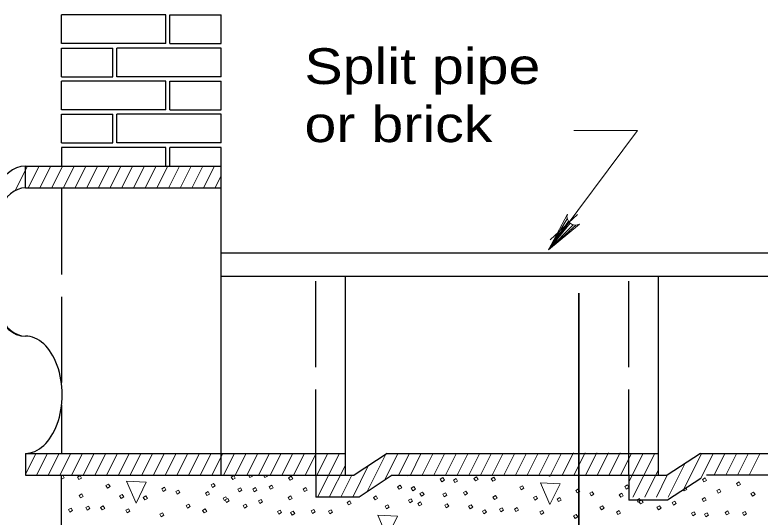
# Model space of a CAD drawing. Extents: x 750.7 to 784.7, y 860.1 to 882.1.
# Drawn here: x 753.794 to 757.13, y 863.297 to 865.543 of the extents above; entities that cross this region are included whole.
import ezdxf

# ---------------------------------------------------------------- set-up
doc = ezdxf.new("R2010")
doc.units = 0
doc.header["$LTSCALE"] = 0.064
doc.linetypes.add('LONG_DASHED', pattern=[7.5, 6, -1.5])
doc.layers.add('1', color=7, linetype='Continuous', lineweight=13)

msp = doc.modelspace()

# ---------------------------------------------------------------- linework, layer by layer
at = {"layer": '1', "lineweight": 25}
for p, q in [((754.71817, 865.41542), (754.71817, 865.5435)), ((754.23292, 865.26717), (754.23292, 865.39525)), ((754.48808, 865.41542), (754.71817, 865.41542)), ((754.00283, 865.26717), (754.23292, 865.26717)), ((754.71817, 865.11892), (754.71817, 865.247)), ((754.23292, 864.97067), (754.23292, 865.09875)), ((754.48808, 865.11892), (754.71817, 865.11892)), ((754.00283, 864.97067), (754.23292, 864.97067)), ((754.47042, 864.95042), (754.00275, 864.95042)), ((754.00275, 864.95042), (754.00275, 864.86825)), ((754.47042, 864.86733), (754.47042, 864.95042)), ((754.48808, 864.86733), (754.48808, 864.95042)), ((754.71817, 864.95042), (754.48808, 864.95042)), ((754.71817, 864.86733), (754.71817, 864.95042)), ((753.84092, 864.86733), (754.71817, 864.86733)), ((753.84092, 864.76942), (753.84092, 864.86733)), ((754.71817, 864.76942), (754.71817, 864.86733)), ((753.84092, 864.76942), (754.71817, 864.76942)), ((754.71817, 864.4795), (757.91908, 864.4795)), ((754.71817, 864.375), (758.05858, 864.375)), ((755.27333, 863.48375), (755.27333, 864.375)), ((756.67542, 863.48367), (756.67542, 864.375)), ((753.84092, 863.58175), (753.84092, 863.48383)), ((753.84092, 863.58175), (755.27333, 863.58175)), ((755.461, 863.58175), (755.3125, 863.48375)), ((755.461, 863.58175), (756.67542, 863.58175)), ((756.86317, 863.58175), (756.71458, 863.48367)), ((756.86317, 863.58175), (758.05858, 863.58175)), ((754.00275, 862.95208), (754.00275, 863.48375)), ((754.71817, 863.48375), (755.3125, 863.48375)), ((755.14075, 863.48375), (755.14075, 863.38575)), ((755.48358, 863.48375), (755.33517, 863.38575)), ((755.48358, 863.48375), (756.67542, 863.48375)), ((756.54283, 863.48367), (756.71458, 863.48367)), ((756.54283, 863.48367), (756.54283, 863.37175)), ((756.86442, 863.46967), (756.71608, 863.37175)), ((757.926, 863.48367), (756.88958, 863.48367)), ((755.33517, 863.38575), (755.14075, 863.38575)), ((756.71608, 863.37175), (756.54283, 863.37175))]:
    msp.add_line(p, q, dxfattribs=at)
at = {"layer": '1'}
for p, q in [((753.79575, 864.7575), (753.85067, 864.86733)), ((753.854, 864.76942), (753.903, 864.86733)), ((753.90633, 864.7695), (753.95525, 864.86733)), ((753.95867, 864.76967), (754.0075, 864.86733)), ((754.01108, 864.76975), (754.05983, 864.86733)), ((754.06317, 864.76942), (754.11208, 864.86733)), ((754.11542, 864.76942), (754.16442, 864.86733)), ((754.16775, 864.76942), (754.21667, 864.86733)), ((754.22, 864.76942), (754.269, 864.86733)), ((754.27233, 864.76942), (754.32125, 864.86733)), ((754.32458, 864.76942), (754.37358, 864.86733)), ((754.37683, 864.76942), (754.42583, 864.86733)), ((754.42917, 864.76942), (754.47808, 864.86733)), ((754.48117, 864.76883), (754.53042, 864.86733)), ((754.5335, 864.769), (754.58267, 864.86733)), ((754.58592, 864.76908), (754.635, 864.86733)), ((754.63825, 864.76925), (754.68725, 864.86733)), ((754.69058, 864.76933), (754.71817, 864.82458)), ((756.26667, 864.63125), (756.18308, 864.49258)), ((756.31217, 864.651), (756.19092, 864.53717)), ((756.27183, 864.62), (756.18308, 864.49258)), ((756.27967, 864.61158), (756.18308, 864.49258)), ((756.29258, 864.60475), (756.18308, 864.49258)), ((756.3045, 864.603), (756.18308, 864.49258)), ((753.84092, 863.488), (753.88783, 863.58175)), ((753.89117, 863.48383), (753.94008, 863.58175)), ((753.94342, 863.48383), (753.99242, 863.58175)), ((753.99575, 863.48383), (754.04467, 863.58175)), ((754.048, 863.48383), (754.097, 863.58175)), ((754.10025, 863.48383), (754.14925, 863.58175)), ((754.15258, 863.48383), (754.2015, 863.58175)), ((754.20483, 863.48383), (754.25383, 863.58175)), ((754.25717, 863.48383), (754.30608, 863.58175)), ((754.30942, 863.48383), (754.35842, 863.58175)), ((754.36175, 863.48383), (754.41067, 863.58175)), ((754.414, 863.48383), (754.463, 863.58175)), ((754.46633, 863.48383), (754.51525, 863.58175)), ((754.51858, 863.48383), (754.56758, 863.58175)), ((754.57083, 863.48383), (754.61983, 863.58175)), ((754.62317, 863.48383), (754.67208, 863.58175)), ((754.67542, 863.48383), (754.72442, 863.58175)), ((754.72775, 863.48383), (754.77667, 863.58175)), ((754.78008, 863.484), (754.829, 863.58175)), ((754.83242, 863.48408), (754.88125, 863.58175)), ((754.88475, 863.48417), (754.93358, 863.58175)), ((754.93708, 863.48433), (754.98583, 863.58175)), ((754.98942, 863.48442), (755.03817, 863.58175)), ((755.04183, 863.4845), (755.09042, 863.58175)), ((755.09417, 863.48467), (755.14267, 863.58175)), ((755.146, 863.48375), (755.195, 863.58175)), ((755.14933, 863.38575), (755.24725, 863.58175)), ((755.36992, 863.40867), (755.45642, 863.58175)), ((755.44792, 863.46017), (755.50875, 863.58192)), ((755.512, 863.48375), (755.56108, 863.582)), ((755.56425, 863.48375), (755.61342, 863.58208)), ((755.61658, 863.48375), (755.66583, 863.58225)), ((755.66883, 863.48375), (755.71817, 863.58233)), ((755.72117, 863.48375), (755.7705, 863.5825)), ((755.77342, 863.48375), (755.82283, 863.58258)), ((755.82567, 863.48375), (755.87517, 863.58267)), ((755.878, 863.48375), (755.9275, 863.58283)), ((755.93025, 863.48375), (755.97983, 863.58292)), ((755.98258, 863.48375), (756.03217, 863.583)), ((756.03483, 863.48375), (756.08458, 863.58317)), ((756.08717, 863.48367), (756.13692, 863.58325)), ((756.13942, 863.48375), (756.18925, 863.58342)), ((756.19175, 863.48367), (756.24158, 863.5835)), ((756.244, 863.48367), (756.29392, 863.58358)), ((756.29625, 863.48367), (756.34625, 863.58375)), ((756.34858, 863.48367), (756.39858, 863.58383)), ((756.40083, 863.48367), (756.45092, 863.58392)), ((756.45317, 863.48367), (756.50333, 863.58408)), ((756.50542, 863.48367), (756.55442, 863.58175)), ((756.54283, 863.454), (756.60675, 863.58175)), ((756.561, 863.38575), (756.659, 863.58175)), ((756.78642, 863.41817), (756.86817, 863.58183)), ((756.86442, 863.46967), (756.9205, 863.58192)), ((756.92375, 863.48367), (756.97283, 863.582)), ((756.976, 863.48367), (757.02525, 863.58217)), ((757.02825, 863.48367), (757.07758, 863.58225)), ((757.08058, 863.48367), (757.12992, 863.58233)), ((755.20158, 863.38575), (755.27333, 863.52933)), ((755.30617, 863.38575), (755.37617, 863.52575)), ((756.71792, 863.38575), (756.79258, 863.53525)), ((756.61333, 863.38575), (756.67542, 863.50992)), ((754.00275, 863.48075), (754.008, 863.48375)), ((755.25383, 863.38575), (755.30283, 863.48375)), ((756.66558, 863.38575), (756.71458, 863.48375)), ((754.73208, 863.37), (754.72592, 863.38083)), ((756.58475, 863.36267), (756.57858, 863.3735))]:
    msp.add_line(p, q, dxfattribs=at)
at = {"layer": '1', "linetype": 'LONG_DASHED', "lineweight": 25}
for p, q in [((754.00275, 864.76642), (754.00275, 863.58175)), ((755.14075, 863.48375), (755.14075, 864.375)), ((756.54283, 863.48367), (756.54283, 864.375))]:
    msp.add_line(p, q, dxfattribs=at)
at = {"layer": '1', "lineweight": 35}
msp.add_line((756.31867, 862.75308), (756.31867, 864.29933), dxfattribs=at)
at = {"layer": '1', "lineweight": 25}
for points in [[(754.47042, 865.4155), (754.47042, 865.5435), (754.00275, 865.5435)], [(754.47042, 865.4155), (754.00275, 865.4155), (754.00275, 865.5435)], [(754.48808, 865.41542), (754.48808, 865.5435), (754.71817, 865.5435)], [(754.00283, 865.26717), (754.00283, 865.39525), (754.23292, 865.39525)], [(754.71817, 865.26717), (754.71817, 865.39525), (754.2505, 865.39525)], [(754.71817, 865.26717), (754.2505, 865.26717), (754.2505, 865.39525)], [(754.47042, 865.11892), (754.47042, 865.247), (754.00275, 865.247)], [(754.47042, 865.11892), (754.00275, 865.11892), (754.00275, 865.247)], [(754.48808, 865.11892), (754.48808, 865.247), (754.71817, 865.247)], [(754.00283, 864.97067), (754.00283, 865.09875), (754.23292, 865.09875)], [(754.71817, 864.97067), (754.71817, 865.09875), (754.2505, 865.09875)], [(754.71817, 864.97067), (754.2505, 864.97067), (754.2505, 865.09875)], [(753.84092, 863.48383), (754.71817, 863.48383), (754.71817, 864.76942)]]:
    msp.add_lwpolyline(points, dxfattribs=at)
at = {"layer": '1'}
for points in [[(756.18308, 864.49258), (756.58175, 865.02675), (756.29592, 865.02675)], [(756.32217, 864.60783), (756.18308, 864.49258), (756.26717, 864.65242)], [(754.0085, 863.48375), (754.01467, 863.47275), (754.00283, 863.466), (754.00275, 863.46617)], [(754.856, 863.48375), (754.858, 863.48017), (754.84617, 863.4735), (754.84033, 863.48375)], [(754.92292, 863.48375), (754.92467, 863.4805), (754.91283, 863.47383), (754.90725, 863.48375)], [(755.554, 863.48375), (755.55075, 863.48183), (755.54967, 863.48375)], [(756.1945, 863.48375), (756.187, 863.47942), (756.18458, 863.48375)], [(756.79908, 863.42658), (756.8025, 863.42058), (756.79067, 863.41383), (756.78775, 863.41908)], [(754.72592, 863.38083), (754.73783, 863.38758), (754.741, 863.38192)], [(756.57858, 863.3735), (756.5905, 863.38025), (756.59367, 863.37458)]]:
    msp.add_lwpolyline(points, dxfattribs=at)
for points in [[(754.07408, 863.4755), (754.08592, 863.48225), (754.09233, 863.471), (754.08042, 863.46425)], [(754.76267, 863.47558), (754.7745, 863.48225), (754.78083, 863.471), (754.769, 863.46433)], [(755.0195, 863.47258), (755.03133, 863.47933), (755.03775, 863.46808), (755.02583, 863.46142)], [(755.6985, 863.4665), (755.71033, 863.47325), (755.71667, 863.462), (755.70483, 863.45525)], [(755.75725, 863.46208), (755.76908, 863.46883), (755.77542, 863.45758), (755.76358, 863.45083)], [(755.84917, 863.46992), (755.861, 863.47667), (755.86742, 863.46542), (755.8555, 863.45867)], [(755.92675, 863.46817), (755.93858, 863.47492), (755.945, 863.46367), (755.93308, 863.45692)], [(756.87217, 863.46525), (756.88408, 863.472), (756.89042, 863.46075), (756.8785, 863.45408)], [(754.20183, 863.43783), (754.21367, 863.4445), (754.22008, 863.43325), (754.20817, 863.42658)], [(754.29417, 863.45725), (754.33675, 863.35975), (754.38233, 863.4535)], [(754.45192, 863.42325), (754.46375, 863.42992), (754.47008, 863.41867), (754.45825, 863.412)], [(754.672, 863.441), (754.68383, 863.44775), (754.69017, 863.4365), (754.67833, 863.42975)], [(754.79208, 863.42142), (754.804, 863.42817), (754.81033, 863.41692), (754.79842, 863.41017)], [(754.85883, 863.42175), (754.87067, 863.4285), (754.877, 863.41725), (754.86517, 863.4105)], [(754.93167, 863.43242), (754.9435, 863.43917), (754.94983, 863.42792), (754.938, 863.42117)], [(755.08392, 863.42233), (755.09583, 863.429), (755.10217, 863.41775), (755.09025, 863.41108)], [(755.50742, 863.43225), (755.51925, 863.439), (755.52558, 863.42775), (755.51375, 863.421)], [(755.56842, 863.42617), (755.58025, 863.43292), (755.58667, 863.42167), (755.57475, 863.41492)], [(756.0545, 863.4305), (756.06633, 863.43717), (756.07275, 863.42592), (756.06083, 863.41925)], [(756.14683, 863.44992), (756.18942, 863.35242), (756.235, 863.44617)], [(756.52467, 863.43367), (756.5365, 863.44042), (756.54283, 863.42917), (756.531, 863.42242)], [(757.024, 863.4475), (757.03592, 863.45425), (757.04225, 863.443), (757.03033, 863.43625)], [(754.08158, 863.39367), (754.09342, 863.40033), (754.09975, 863.38908), (754.08792, 863.38242)], [(754.263, 863.39142), (754.27483, 863.39817), (754.28117, 863.38692), (754.26933, 863.38017)], [(754.36883, 863.38467), (754.38067, 863.39142), (754.387, 863.38017), (754.37517, 863.37342)], [(754.51442, 863.41075), (754.52625, 863.4175), (754.53258, 863.40625), (754.52075, 863.3995)], [(754.64683, 863.40417), (754.65867, 863.41092), (754.665, 863.39967), (754.65317, 863.39292)], [(755.01733, 863.38458), (755.02925, 863.39133), (755.03558, 863.38008), (755.02375, 863.37333)], [(755.39983, 863.38475), (755.41167, 863.39142), (755.418, 863.38017), (755.40617, 863.3735)], [(755.60742, 863.40208), (755.61925, 863.40883), (755.62558, 863.39758), (755.61375, 863.39092)], [(755.70958, 863.39883), (755.72142, 863.4055), (755.72775, 863.39425), (755.71592, 863.38758)], [(755.8015, 863.40658), (755.81333, 863.41333), (755.81967, 863.40208), (755.80783, 863.39542)], [(755.93425, 863.38633), (755.94608, 863.393), (755.95242, 863.38175), (755.94058, 863.37508)], [(756.30458, 863.41592), (756.31642, 863.42258), (756.32275, 863.41133), (756.31092, 863.40467)], [(756.36708, 863.40342), (756.37892, 863.41017), (756.38525, 863.39892), (756.37342, 863.39217)], [(756.4995, 863.39683), (756.51133, 863.40358), (756.51767, 863.39233), (756.50583, 863.38558)], [(756.93658, 863.415), (756.9485, 863.42167), (756.95483, 863.41042), (756.943, 863.40375)], [(757.089, 863.40217), (757.10083, 863.40892), (757.10717, 863.39767), (757.09533, 863.39092)], [(754.73508, 863.374), (754.74692, 863.38067), (754.75325, 863.36942), (754.74142, 863.36275)], [(754.88392, 863.36917), (754.89583, 863.37583), (754.90217, 863.36458), (754.89025, 863.35792)], [(755.28133, 863.36258), (755.29317, 863.36933), (755.2995, 863.35808), (755.28767, 863.35133)], [(755.55625, 863.37233), (755.56808, 863.37908), (755.57442, 863.36783), (755.56258, 863.36108)], [(755.598, 863.35775), (755.60983, 863.3645), (755.61617, 863.35325), (755.60433, 863.3465)], [(756.11567, 863.38408), (756.1275, 863.39083), (756.13383, 863.37958), (756.122, 863.37283)], [(756.2215, 863.37742), (756.23333, 863.38408), (756.23967, 863.37283), (756.22783, 863.36617)], [(756.58775, 863.36667), (756.59958, 863.37333), (756.60592, 863.36208), (756.59408, 863.35542)], [(756.73658, 863.36183), (756.7485, 863.3685), (756.75483, 863.35725), (756.743, 863.35058)], [(756.87, 863.37725), (756.88192, 863.384), (756.88825, 863.37275), (756.87642, 863.366)], [(754.03383, 863.33033), (754.04575, 863.33708), (754.05208, 863.32583), (754.04025, 863.31908)], [(754.111, 863.3395), (754.12283, 863.34625), (754.12917, 863.335), (754.11733, 863.32825)], [(754.17775, 863.33983), (754.18958, 863.34658), (754.19592, 863.33533), (754.18408, 863.32858)], [(754.29075, 863.32742), (754.30258, 863.33417), (754.30892, 863.32292), (754.29708, 863.31617)], [(754.5605, 863.3485), (754.57233, 863.35517), (754.57867, 863.34392), (754.56683, 863.33725)], [(754.63442, 863.3265), (754.64625, 863.33325), (754.65258, 863.322), (754.64075, 863.31525)], [(754.81558, 863.34792), (754.82742, 863.35467), (754.83375, 863.34342), (754.82192, 863.33667)], [(754.96967, 863.32133), (754.9815, 863.32808), (754.98783, 863.31683), (754.976, 863.31008)], [(755.12042, 863.32475), (755.13225, 863.33142), (755.13858, 863.32017), (755.12675, 863.3135)], [(755.198, 863.323), (755.20983, 863.32975), (755.21617, 863.3185), (755.20433, 863.31175)], [(755.45183, 863.3455), (755.46367, 863.35225), (755.47, 863.341), (755.45817, 863.33425)], [(755.718, 863.34992), (755.72983, 863.35658), (755.73617, 863.34542), (755.72433, 863.33867)], [(755.82525, 863.34533), (755.83717, 863.352), (755.8435, 863.34075), (755.83167, 863.33408)], [(755.88658, 863.323), (755.89842, 863.32975), (755.90475, 863.3185), (755.89292, 863.31175)], [(755.96367, 863.33217), (755.9755, 863.33892), (755.98183, 863.32767), (755.97, 863.32092)], [(756.03042, 863.3325), (756.04225, 863.33925), (756.04858, 863.328), (756.03675, 863.32133)], [(756.14342, 863.32008), (756.15525, 863.32683), (756.16158, 863.31558), (756.14975, 863.30883)], [(756.41317, 863.34117), (756.425, 863.34783), (756.43133, 863.33658), (756.4195, 863.32992)], [(756.48708, 863.31917), (756.49892, 863.32592), (756.50525, 863.31467), (756.49342, 863.30792)], [(756.66825, 863.34058), (756.68008, 863.34733), (756.68642, 863.33608), (756.67458, 863.32933)], [(754.44258, 863.30967), (754.45442, 863.31633), (754.46075, 863.30508), (754.44892, 863.29842)], [(755.02842, 863.31692), (755.04025, 863.32367), (755.04658, 863.31242), (755.03475, 863.30567)], [(755.41808, 863.30467), (755.46058, 863.20725), (755.50625, 863.301)], [(756.29525, 863.30233), (756.30708, 863.309), (756.31342, 863.29775), (756.30158, 863.29108)], [(756.82233, 863.314), (756.83417, 863.32075), (756.8405, 863.3095), (756.82867, 863.30275)], [(756.88108, 863.30958), (756.89292, 863.31633), (756.89925, 863.30508), (756.88742, 863.29833)], [(756.97308, 863.31742), (756.98492, 863.32408), (756.99125, 863.31283), (756.97942, 863.30617)], [(757.05067, 863.31567), (757.0625, 863.32242), (757.06883, 863.31117), (757.057, 863.30442)]]:
    msp.add_lwpolyline(points, close=True, dxfattribs=at)
msp.add_arc((756.30365, 864.64125), 0.03822, 163.03179, 298.85792, dxfattribs=at)
at = {"layer": '1', "lineweight": 25}
for centre, major_axis, ratio, start_param, end_param in [((753.84094, 864.48688), (0, 0.38047), 0.513686, 0.0000003, 3.1415929), ((753.84094, 864.4379), (0, 0.33149), 0.513686, 0.0000003, 3.1415929), ((753.84094, 863.8441), (0, 0.26231), 0.62784, 3.1415929, 6.2831856)]:
    msp.add_ellipse(centre, major_axis=major_axis, ratio=ratio, start_param=start_param, end_param=end_param, dxfattribs=at)

# ---------------------------------------------------------------- texts
at = {"layer": '1', "width": 1.2}
for s, p in [('Split pipe', (755.09017, 865.23433)), ('or brick', (755.09017, 864.97433))]:
    msp.add_text(s, height=0.16, dxfattribs=at).set_placement(p)

doc.saveas('drawing.dxf')
